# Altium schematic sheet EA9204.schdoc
size 127 x 101 mm
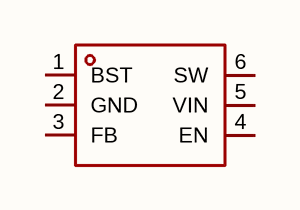
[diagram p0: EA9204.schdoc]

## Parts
U?  ea9204  [SOT-23-6_L2.9-W1.6-P0.95-LS2.8-BL_3]  (value not drawn)

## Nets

Not connected (* = marked no-connect by the designer): U? 1(BST) 2(GND) 3(FB) 4(EN) 5(VIN) 6(SW)

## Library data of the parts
U? = ea9204: 功能类型:降压型;工作电压:4V~30V;输出电压:-;输出电流:1.5A;输出类型:可调;; Manufacturer: everanalog(申风); AddInBom: yes; ModelId: fb8f66c7218e47258c3712467298ba04; ModelTransform: 114.173,110.236,0,0,0,0,0,0,0; Function: 降压型; Voltage - Supply: 4V~30V; Output Current: 1.5A; Frequency - Switching: 1MHz~2MHz; Synchronous Rectifier: 是; Number of Outputs: 1; Topology: 降压式; Quiescent Current: 13mA; Switch tube (built-in/external): 内置; Output Type: 可调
